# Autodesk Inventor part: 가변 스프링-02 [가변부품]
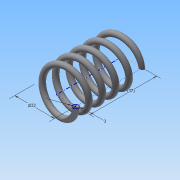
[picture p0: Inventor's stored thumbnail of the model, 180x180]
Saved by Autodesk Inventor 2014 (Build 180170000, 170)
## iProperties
Created: 2015-09
Part Number: 가변 스프링-02 [가변부품]
Material: 강철, 탄소
Document SubType Name: Modeling
Designer: study
Density: 7.87 g/cm^3
Appearance: 반연마
Mass: 18.9204 g
Surface Area: 32.5878 cm^2
Volume: 2.40412 cm^3
Author: study
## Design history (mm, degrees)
sketch "스케치1"
  geometry: L1 (0, 0)-(11, 0); L2 (11, 0)-(11, 40.761); L3 (11, 40.761)-(0, 40.761); L4 (0, 40.761)-(0, 0); C1 r 1.5 at (11, 0)
  constraints: 8 end point, 2 parallel, 1 centre point, 1 coincident, 1 horizontal, 1 perpendicular
  dimensions: "d0" = 22 diameter of L2 L4; "d1" = 3 diameter of C1; "d2" = 40.7612 distance between parallel lines of L3 L1 (derived)
feature "코일1" sketch "스케치1" pitch "d3" = 10; turns "d5" = 5; dims "d4" = 40.7612 (= d2), "d6" = 0, angle "d7" = 90 deg, angle "d8" = 90 deg, "d9" = 0, "d10" = 0
node "작업 평면1"
sketch "스케치2"
  geometry: L1 (-12.5, 0)-(-9.5, 0) reference; 1 further point
  constraints: 1 horizontal alignment
extrude "돌출1" cut sketch "스케치2" stored distance "d12" = 10; taper "d13" = 0 deg
node "작업 평면2"
sketch "스케치3"
  geometry: L1 (-9.5, 0)-(-12.5, 0) reference; L2 (-9.5, 0)-(-12.5, 0) reference; 1 further point
  constraints: 2 horizontal alignment
extrude "돌출2" cut sketch "스케치3" stored distance "d15" = 10; taper "d16" = 0 deg
node "솔리드1"
node "절단 모서리 투영1"
node "절단 모서리 투영2"
node "절단 모서리 투영3"
other parameters: "d11" = 0, "d14" = 40.7612 (= d2)
